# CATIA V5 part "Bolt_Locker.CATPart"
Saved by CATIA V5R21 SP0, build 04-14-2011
Part number: Bolt_Holder
Bounding box of the stored display mesh (mm): x -89 to 89, y -7 to 7, z 0 to 2.8
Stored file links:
  C:\Users\Pouria\Desktop\Box\Bolt_Locker.CATPart
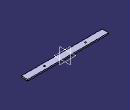
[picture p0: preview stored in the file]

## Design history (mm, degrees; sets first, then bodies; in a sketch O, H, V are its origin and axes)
Body1 (main body)
  Sketch1 on xy-plane, origin (0, 0, 0), H (1, 0, 0), V (0, 1, 0)
    line L1 (89, 7) -> (89, -7)
    line L2 (89, -7) -> (-89, -7)
    line L3 (-89, -7) -> (-89, 7)
    line L4 (-89, 7) -> (89, 7)
    circle A1 centre (45, 0) radius 1.5
    point P5 (45, 0)
    circle A2 centre (-45, 0) radius 1.5
    point P6 (-45, 0)
    length L4 = 178
    length L1 = 14
    distance P6 L3 = 44
    distance P5 L1 = 44
    radius A1 = 1.5
    radius A2 = 1.5
    vertical: L1 V, L3 V
    horizontal: L2 H, L4 H
    equidistance: L1 L3 O, L2 L4 O
    coincidence: P5 H, P6 H
  Pad1: profile Sketch1, direction (0, 0, 1), length 2.8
